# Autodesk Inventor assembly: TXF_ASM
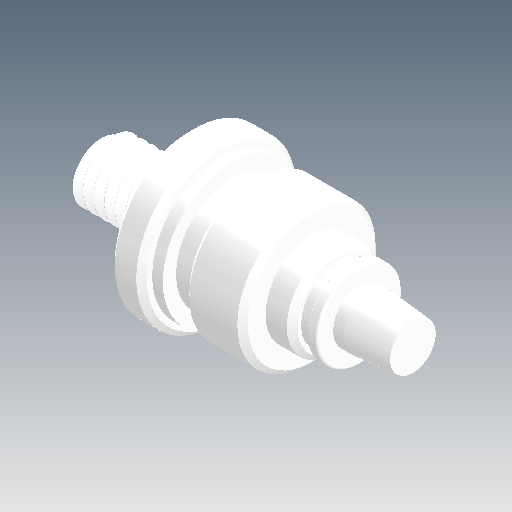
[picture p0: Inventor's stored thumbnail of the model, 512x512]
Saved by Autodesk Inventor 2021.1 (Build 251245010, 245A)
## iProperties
Created: 2021-05
Part Number: TXF_ASM
Document SubType Name: Assembly
Designer: user
Author: user
Revision Number: ÈÎºÎ
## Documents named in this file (3)
- D:\Vault_2016\Projekty\Clamptek\Hydraulic\CHLC\CHLC-40\Inventor\CHLC-MF40\TXF_ASM.iam
- D:\Vault_2016\Projekty\Clamptek\Hydraulic\CHLC\CHLC-40\Inventor\CHLC-MF40\TXF-02.ipt
- D:\Vault_2016\Projekty\Clamptek\Hydraulic\CHLC\CHLC-40\Inventor\CHLC-MF40\TSF-01.ipt
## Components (2 placed, 2 different names)
1. TXF-02_21
2. TSF-01_22
